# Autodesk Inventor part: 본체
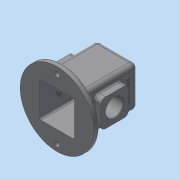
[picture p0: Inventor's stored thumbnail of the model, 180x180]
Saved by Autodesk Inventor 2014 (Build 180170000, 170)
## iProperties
Created: 2021-08
Part Number: 본체
Material: 일반
Document SubType Name: Modeling
Designer: dg
Density: 1 g/cm^3
Appearance: 기본값
Author: dg
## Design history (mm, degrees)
sketch "스케치2"
  geometry: L1 (-37, 37)-(37, 37); L2 (37, 37)-(37, -37); L3 (37, -37)-(-37, -37); L4 (-37, -37)-(-37, 37); 3 further points
  constraints: 8 end point, 2 midpoint, 2 parallel, 2 perpendicular, 1 horizontal, 1 horizontal alignment, 1 vertical alignment
  dimensions: "d2" = 74 distance of L1.start L1.end
extrude "돌출1" new body sketch "스케치2" stored distance "d3" = 110; taper "d4" = 0 deg
sketch "스케치3"
  geometry: L1 (-25, 25)-(25, 25); L2 (25, 25)-(25, -25); L3 (25, -25)-(-25, -25); L4 (-25, -25)-(-25, 25); 3 further points
  constraints: 8 end point, 2 midpoint, 2 parallel, 2 perpendicular, 1 horizontal, 1 horizontal alignment, 1 vertical alignment
  dimensions: "d5" = 50 distance of L1.start L1.end
extrude "돌출2" join sketch "스케치3" stored distance "d6" = 100; taper "d7" = 0 deg
sketch "스케치4"
  geometry: L1 (37, 37)-(-37, 37) reference; L2 (-37, 37)-(-37, -37) reference; L3 (-37, -37)-(37, -37) reference; L4 (37, -37)-(37, 37) reference; L5 (-32, 32)-(32, 32); L6 (32, 32)-(32, -32); L7 (32, -32)-(-32, -32); L8 (-32, -32)-(-32, 32); 1 further point
  constraints: 8 end point, 3 other
  dimensions: "d8" = 64 distance of L5.start L5.end
extrude "돌출3" cut sketch "스케치4" distance "d9" = 105; taper "d10" = 0 deg
sketch "스케치5"
  geometry: L1 (37, 37)-(-37, 37) reference; L2 (-37, 37)-(-37, -37) reference; L3 (-37, -37)-(37, -37) reference; L4 (37, -37)-(37, 37) reference; C1 r 67 at (0, 0); C2 r 4.5 at (0, 55); C3 r 4.5 at (0, -55); A1 r 55 centre (0, 0) between (0, 55) and (0, -55); 1 further point
  constraints: 4 centre point, 2 coincident, 2 point on circle, 2 vertical alignment, 1 equal radius
  dimensions: "d11" = 134 diameter of C1; "d12" = 110 diameter of A1; "d13" = 9 diameter of C2
extrude "돌출4" join sketch "스케치5" distance "d14" = 10; taper "d15" = 0 deg
sketch "스케치6"
  geometry: L1 (37, 55)-(-37, 55) reference; L2 (0, 55)-(0, 65); L3 (0, 65)-(-20, 65); L4 (-20, 65)-(-21.051, 55); 1 further point
  constraints: 6 end point, 2 perpendicular, 1 midpoint, 1 point on line
  dimensions: "d16" = 96 deg angle of L1 L4; "d17" = 10 distance between parallel lines of L1 L3; "d18" = 40 diameter of L3.end L2
revolve "회전1" sketch "스케치6" stored, may be unused: angle "d19" = 90 deg
hole "구멍1" diameter "d22" = 21; stored, may be unused: countersink angle "d26" = 90 deg, drill point angle "d28" = 118 deg; dims "d20" = 10, "d21" = 10, "d23" = 6, "d24" = 28, "d25" = 4, "d27" = 8
sketch "스케치7"
  geometry: L1 (-32, -55)-(-32, 50) reference; L2 (32, -55)-(32, 50) reference; L3 (-32, 0)-(32, 0); L4 (-32, 25)-(-25, 22.452); L5 (-25, 22.452)-(-25, 0); L6 (32, 25)-(25, 22.452); L7 (25, 22.452)-(25, 0); 2 further points
  constraints: 10 end point, 6 point on line, 3 perpendicular, 1 coincident, 1 midpoint, 1 parallel
  dimensions: "d29" = 50 diameter of L4.start L3; "d30" = 110 deg angle of L1 L4; "d32" = 7 distance between parallel lines of L1 L5; "d33" = 110 deg angle of L2 L6; "d34" = 50 diameter of L6.start L3
revolve "회전2" sketch "스케치7" stored, may be unused: angle "d35" = 90 deg
fillet "모깎기1" dims "d36" = 8
fillet "모깎기2" dims "d37" = 3
sketch "스케치8"
  geometry: C1 r 16 at (0, 0); A1 r 8 centre (-17, -17) between (-25, -17) and (-17, -25) reference; A2 r 8 centre (17, -17) between (17, -25) and (25, -17) reference; A3 r 8 centre (17, 17) between (25, 17) and (17, 25) reference; A4 r 8 centre (-17, 17) between (-17, 25) and (-25, 17) reference; 5 further points
  constraints: 5 coincident, 1 centre point
  dimensions: "d38" = 32 diameter of C1
extrude "돌출5" cut sketch "스케치8" stored distance "d39" = 10; taper "d40" = 0 deg
hole "구멍2" sketch "스케치8" diameter "d41" = 3.242; stored, may be unused: countersink angle "d45" = 90 deg, drill point angle "d47" = 118 deg; dims "d42" = 8, "d43" = 28, "d44" = 4, "d46" = 10
node "작업 평면1"
chamfer "모따기1" distance "d48" = 1; stored, may be unused: second distance "d49" = 2, angle "d50" = 45 deg
sketch "스케치9"
  geometry: L1 (-8, 0)-(-8, -89) reference; L2 (49, 18)-(9, 18) reference; 2 further points
  constraints: 1 other
  dimensions: "d51" = 37 distance from line of L1 point (29, -10); "d52" = 28 distance from line of L2 point (29, -10)
feature "엠보싱1" sketch "스케치9" dims "d2" = 74, "d8" = 64, "d53" = 0.5, "d54" = 0
node "솔리드1"
mirror "대칭1"
